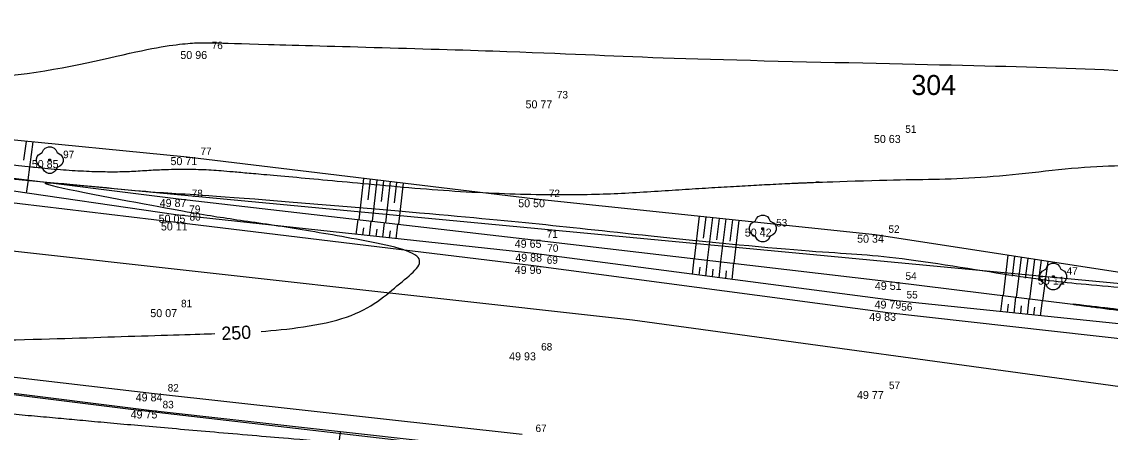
# Model space of a CAD drawing. Extents: x -704057 to -703795, y -1008732 to -1008584.
# Drawn here: x -703875.92 to -703835.12, y -1008671.22 to -1008655.82 of the extents above; entities that cross this region are included whole.
import ezdxf

# ---------------------------------------------------------------- set-up
doc = ezdxf.new("R2010")
doc.units = 0
for name, color, linetype in [('Z_body', 7, 'Continuous'), ('Z_body_cisla', 7, 'Continuous'), ('Z_body_vysky', 7, 'Continuous'), ('Z_katastr_cisla_pozemkove', 7, 'Continuous'), ('Z_katastr_hranice', 7, 'Continuous'), ('Z_katastr_hranice_KU', 7, 'Continuous'), ('Z_komunikace_zpevn_pl', 7, 'Continuous'), ('Z_teren_hrany_paty', 7, 'Continuous'), ('Z_vrstevnice_popis', 7, 'Continuous'), ('Z_vrstevnice_vedlejsi', 7, 'Continuous'), ('Z_zelen_jednotliva', 7, 'Continuous')]:
    doc.layers.add(name, color=color, linetype=linetype)

# ---------------------------------------------------------------- blocks, each defined once
blk = doc.blocks.new('POINT_DISPLAY')
blk.add_line((0, 0), (0, 0))
blk = doc.blocks.new('Z24')
for p, q in [((-0.23, 0.38), (-0.17, 0.45)), ((-0.17, 0.45), (-0.05, 0.5)), ((-0.05, 0.5), (0.05, 0.5)), ((0.05, 0.5), (0.17, 0.45)), ((0.17, 0.45), (0.23, 0.38)), ((-0.5, 0.05), (-0.47, 0.13)), ((-0.5, -0.05), (-0.5, 0.05)), ((-0.47, 0.13), (-0.42, 0.2)), ((-0.42, 0.2), (-0.28, 0.28)), ((-0.28, 0.28), (-0.23, 0.38)), ((-0.03, -0.03), (-0.03, 0.03)), ((-0.03, 0.03), (0.03, 0.03)), ((0.03, 0.03), (0.03, -0.03)), ((0.23, 0.38), (0.28, 0.28)), ((0.28, 0.28), (0.42, 0.2)), ((0.42, 0.2), (0.47, 0.13)), ((0.47, 0.13), (0.5, 0.05)), ((0.5, 0.05), (0.5, -0.05)), ((-0.45, -0.17), (-0.5, -0.05)), ((-0.38, -0.23), (-0.45, -0.17)), ((-0.28, -0.28), (-0.38, -0.23)), ((-0.2, -0.42), (-0.28, -0.28)), ((0.03, -0.03), (-0.03, -0.03)), ((0.28, -0.28), (0.2, -0.42)), ((0.38, -0.23), (0.28, -0.28)), ((0.45, -0.17), (0.38, -0.23)), ((0.5, -0.05), (0.45, -0.17)), ((-0.13, -0.47), (-0.2, -0.42)), ((-0.05, -0.5), (-0.13, -0.47)), ((0.05, -0.5), (-0.05, -0.5)), ((0.13, -0.47), (0.05, -0.5)), ((0.2, -0.42), (0.13, -0.47))]:
    blk.add_line(p, q)

msp = doc.modelspace()

# ---------------------------------------------------------------- linework, layer by layer
at = {"layer": 'Z_katastr_hranice'}
for p, q in [((-703892.72, -1008660.17), (-703821.1, -1008666.93)), ((-703907.73, -1008665.91), (-703871.83, -1008670.35)), ((-703871.83, -1008670.35), (-703828.51, -1008675.34))]:
    msp.add_line(p, q, dxfattribs=at)
at = {"layer": 'Z_katastr_hranice_KU'}
for p, q in [((-703906.73, -1008661.04), (-703853.02, -1008667)), ((-703853.02, -1008667), (-703796.88, -1008674.69))]:
    msp.add_line(p, q, dxfattribs=at)
at = {"layer": 'Z_komunikace_zpevn_pl'}
for p, q in [((-703870.13, -1008663.35), (-703882.46, -1008661.89)), ((-703856.74, -1008664.98), (-703870.13, -1008663.35)), ((-703843.45, -1008666.74), (-703856.74, -1008664.98)), ((-703832.57, -1008667.96), (-703843.45, -1008666.74)), ((-703883, -1008668.36), (-703870.95, -1008669.76)), ((-703870.95, -1008669.76), (-703857.16, -1008671.29))]:
    msp.add_line(p, q, dxfattribs=at)
at = {"layer": 'Z_teren_hrany_paty'}
for p, q in [((-703869.72, -1008660.9), (-703882.16, -1008659.68)), ((-703875.76, -1008660.31), (-703875.85, -1008661.02)), ((-703875.51, -1008660.33), (-703875.69, -1008661.75)), ((-703882.42, -1008660.9), (-703870.05, -1008662.47)), ((-703856.66, -1008662.48), (-703869.72, -1008660.9)), ((-703870.14, -1008663.06), (-703882.51, -1008661.26)), ((-703875.74, -1008662.25), (-703875.67, -1008661.76)), ((-703863.11, -1008661.7), (-703863.29, -1008663.25)), ((-703862.86, -1008661.73), (-703862.95, -1008662.5)), ((-703862.61, -1008661.76), (-703862.79, -1008663.3)), ((-703862.36, -1008661.79), (-703862.45, -1008662.56)), ((-703862.11, -1008661.82), (-703862.29, -1008663.36)), ((-703861.87, -1008661.85), (-703861.96, -1008662.62)), ((-703861.62, -1008661.88), (-703861.8, -1008663.42)), ((-703870.05, -1008662.47), (-703856.74, -1008664)), ((-703843.93, -1008663.81), (-703856.66, -1008662.48)), ((-703856.72, -1008664.52), (-703870.14, -1008663.06)), ((-703863.38, -1008663.8), (-703863.31, -1008663.24)), ((-703850.53, -1008663.12), (-703850.71, -1008664.71)), ((-703850.28, -1008663.15), (-703850.37, -1008663.94)), ((-703850.03, -1008663.17), (-703850.22, -1008664.77)), ((-703849.78, -1008663.2), (-703849.87, -1008664)), ((-703849.53, -1008663.22), (-703849.72, -1008664.82)), ((-703849.28, -1008663.25), (-703849.38, -1008664.05)), ((-703863.13, -1008663.82), (-703863.1, -1008663.55)), ((-703862.88, -1008663.85), (-703862.82, -1008663.3)), ((-703862.63, -1008663.88), (-703862.6, -1008663.6)), ((-703862.38, -1008663.9), (-703862.32, -1008663.36)), ((-703862.14, -1008663.93), (-703862.1, -1008663.66)), ((-703861.89, -1008663.96), (-703861.82, -1008663.42)), ((-703849.04, -1008663.28), (-703849.22, -1008664.88)), ((-703856.74, -1008664), (-703843.29, -1008665.58)), ((-703832.19, -1008665.63), (-703843.93, -1008663.81)), ((-703843.25, -1008666.28), (-703856.72, -1008664.52)), ((-703850.77, -1008665.3), (-703850.71, -1008664.71)), ((-703850.28, -1008665.36), (-703850.21, -1008664.77)), ((-703849.78, -1008665.43), (-703849.71, -1008664.83)), ((-703849.29, -1008665.49), (-703849.22, -1008664.88)), ((-703838.95, -1008664.58), (-703839.13, -1008666.09)), ((-703838.7, -1008664.62), (-703838.79, -1008665.37)), ((-703838.45, -1008664.66), (-703838.64, -1008666.15)), ((-703838.21, -1008664.7), (-703838.3, -1008665.44)), ((-703837.96, -1008664.74), (-703838.14, -1008666.22)), ((-703837.71, -1008664.77), (-703837.8, -1008665.51)), ((-703837.46, -1008664.81), (-703837.65, -1008666.28)), ((-703850.53, -1008665.33), (-703850.49, -1008665.03)), ((-703850.03, -1008665.39), (-703850, -1008665.1)), ((-703849.53, -1008665.46), (-703849.5, -1008665.16)), ((-703843.29, -1008665.58), (-703832.35, -1008666.93)), ((-703839.22, -1008666.69), (-703839.14, -1008666.09)), ((-703832.45, -1008667.39), (-703843.25, -1008666.28)), ((-703838.97, -1008666.72), (-703838.93, -1008666.42)), ((-703838.72, -1008666.75), (-703838.65, -1008666.15)), ((-703838.47, -1008666.77), (-703838.44, -1008666.48)), ((-703838.22, -1008666.8), (-703838.15, -1008666.21)), ((-703837.98, -1008666.82), (-703837.94, -1008666.53)), ((-703837.73, -1008666.85), (-703837.66, -1008666.28)), ((-703871.14, -1008670.4), (-703883.02, -1008668.93)), ((-703857.13, -1008671.96), (-703871.14, -1008670.4)), ((-703863.99, -1008671.2), (-703864.17, -1008672.74))]:
    msp.add_line(p, q, dxfattribs=at)
at = {"layer": 'Z_vrstevnice_popis'}
for points in [[(-703900.886, -1008655.959), (-703899.024, -1008656.26), (-703894.071, -1008657.056), (-703890.313, -1008657.487), (-703881.983, -1008657.824), (-703876.324, -1008658.109), (-703871.084, -1008656.76), (-703869.237, -1008656.583), (-703868.601, -1008656.623), (-703856.36, -1008656.952), (-703852.392, -1008657.193), (-703842.819, -1008657.404), (-703836.655, -1008657.542), (-703831.19, -1008657.812), (-703826.999, -1008658.179), (-703824.254, -1008658.442), (-703823.966, -1008658.47)], [(-703866.94, -1008667.434), (-703866.032, -1008667.372), (-703863.34, -1008667.075), (-703861.725, -1008665.569), (-703860.311, -1008664.545), (-703863.717, -1008663.91), (-703866.193, -1008663.489), (-703868.465, -1008663.178), (-703870.115, -1008662.896), (-703877.36, -1008661.542), (-703870.689, -1008662.276), (-703869.999, -1008662.227), (-703861.026, -1008662.976), (-703856.707, -1008663.374), (-703852.831, -1008663.809), (-703845.902, -1008664.503), (-703843.668, -1008664.535), (-703838.357, -1008665.417), (-703836.381, -1008665.655), (-703832.233, -1008665.983), (-703829.782, -1008666.213), (-703825.08, -1008666.738), (-703823.448, -1008666.921)], [(-703935.451, -1008665.426), (-703935.149, -1008665.04), (-703935.119, -1008664.898), (-703935.079, -1008664.688), (-703934.778, -1008664.597), (-703933.704, -1008664.644), (-703930.729, -1008663.86), (-703930.56, -1008663.863), (-703922.686, -1008664.709), (-703917.99, -1008665.148), (-703912.22, -1008665.818), (-703907.01, -1008666.385), (-703897.89, -1008667.322), (-703895.624, -1008667.536), (-703894.683, -1008667.62), (-703889.646, -1008668.109), (-703886.88, -1008668.055), (-703885.948, -1008667.981), (-703882.942, -1008667.846), (-703876.005, -1008667.766), (-703871.926, -1008667.612), (-703869.247, -1008667.54), (-703868.688, -1008667.52)]]:
    msp.add_open_spline(points, degree=3, dxfattribs=at)
at = {"layer": 'Z_vrstevnice_vedlejsi'}
for points in [[(-703944.218, -1008669.537), (-703942.215, -1008669.847), (-703941.835, -1008669.79), (-703940.983, -1008669.911), (-703940.538, -1008669.059), (-703940.441, -1008669.011), (-703939.659, -1008668.87), (-703938.392, -1008666.573), (-703937.218, -1008665.198), (-703936.994, -1008664.158), (-703936.811, -1008663.182), (-703935.504, -1008662.788), (-703930.851, -1008662.989), (-703930.683, -1008662.945), (-703930.514, -1008662.948), (-703928.53, -1008663.14), (-703926.451, -1008662.869), (-703924.285, -1008662.962), (-703918.453, -1008660.188), (-703917.529, -1008662.583), (-703908.804, -1008661.73), (-703914.417, -1008658.58), (-703914.255, -1008657.775), (-703916.458, -1008657.408), (-703916.075, -1008656.975), (-703916.505, -1008656.883), (-703916.435, -1008655.703), (-703915.746, -1008656.007), (-703915.438, -1008656.225), (-703913.541, -1008656.36), (-703913.202, -1008656.502), (-703907.93, -1008657.256), (-703905.824, -1008657.417), (-703900.033, -1008658.024), (-703894.345, -1008658.848), (-703890.179, -1008659.57), (-703887.702, -1008659.871), (-703882.266, -1008660.175), (-703878.347, -1008660.959), (-703873.149, -1008661.531), (-703869.803, -1008661.293), (-703867.148, -1008661.514), (-703856.66, -1008662.48), (-703848.555, -1008661.935), (-703843.582, -1008661.747), (-703840.018, -1008661.713), (-703835.656, -1008661.182), (-703832.168, -1008661.259), (-703831.497, -1008661.293), (-703819.488, -1008662.346), (-703817.521, -1008662.543), (-703807.841, -1008663.114), (-703805.78, -1008663.132)], [(-703806.645, -1008669.413), (-703810.064, -1008669.091), (-703818.896, -1008668.231), (-703821.949, -1008667.886), (-703832.348, -1008666.911), (-703832.429, -1008666.905), (-703837.82, -1008666.255), (-703832.713, -1008666.908), (-703832.355, -1008666.952), (-703825.705, -1008667.99), (-703819.056, -1008669.026), (-703815.993, -1008669.415), (-703810.462, -1008670.24), (-703806.87, -1008671.09), (-703808.766, -1008673.591), (-703809.75, -1008673.886), (-703817.454, -1008673.52), (-703819.628, -1008673.248), (-703826.836, -1008673.24), (-703833.27, -1008673.353), (-703835.286, -1008673.278), (-703844.44, -1008672.81), (-703850.152, -1008672.821), (-703855.806, -1008672.275), (-703857.13, -1008672.165), (-703860.162, -1008671.947), (-703871.237, -1008671.005), (-703876.973, -1008670.473), (-703883.276, -1008669.953), (-703888.652, -1008669.207), (-703892.007, -1008668.787), (-703895.701, -1008668.459), (-703900.931, -1008667.965), (-703907.22, -1008668.487), (-703913.351, -1008668.979), (-703918.495, -1008669.549), (-703927.701, -1008668.863), (-703930.6, -1008669.724), (-703932.124, -1008670.909), (-703936.972, -1008673.376)]]:
    msp.add_open_spline(points, degree=2, dxfattribs=at)

# ---------------------------------------------------------------- block references
at = {"layer": 'Z_body'}
for p in [(-703869.3, -1008656.92), (-703856.36, -1008658.77), (-703843.3, -1008660.07), (-703874.87, -1008661.01), (-703869.72, -1008660.9), (-703870.05, -1008662.47), (-703856.66, -1008662.48), (-703870.14, -1008663.06), (-703870.13, -1008663.35), (-703848.14, -1008663.58), (-703856.74, -1008664), (-703843.93, -1008663.81), (-703856.72, -1008664.52), (-703856.74, -1008664.98), (-703843.29, -1008665.58), (-703837.25, -1008665.38), (-703843.25, -1008666.28), (-703870.45, -1008666.6), (-703843.45, -1008666.74), (-703856.95, -1008668.22), (-703870.95, -1008669.76), (-703843.91, -1008669.67), (-703871.14, -1008670.4)]:
    msp.add_blockref('POINT_DISPLAY', p, dxfattribs=at)
at = {"layer": 'Z_zelen_jednotliva'}
for p in [(-703874.87, -1008661.01), (-703848.14, -1008663.58), (-703837.25, -1008665.38)]:
    msp.add_blockref('Z24', p, dxfattribs=at)

# ---------------------------------------------------------------- texts
at = {"layer": 'Z_body_cisla'}
for s, p in [('76', (-703868.8, -1008656.85)), ('73', (-703855.86, -1008658.7)), ('51', (-703842.8, -1008659.99)), ('97', (-703874.37, -1008660.94)), ('77', (-703869.22, -1008660.82)), ('78', (-703869.55, -1008662.4)), ('72', (-703856.16, -1008662.4)), ('79', (-703869.64, -1008662.99)), ('80', (-703869.63, -1008663.28)), ('53', (-703847.64, -1008663.5)), ('71', (-703856.24, -1008663.93)), ('52', (-703843.43, -1008663.74)), ('70', (-703856.22, -1008664.45)), ('69', (-703856.24, -1008664.9)), ('54', (-703842.79, -1008665.5)), ('47', (-703836.75, -1008665.31)), ('55', (-703842.75, -1008666.2)), ('81', (-703869.95, -1008666.53)), ('56', (-703842.95, -1008666.66)), ('68', (-703856.45, -1008668.15)), ('57', (-703843.41, -1008669.6)), ('82', (-703870.45, -1008669.69)), ('83', (-703870.64, -1008670.32)), ('67', (-703856.66, -1008671.21))]:
    msp.add_text(s, height=0.28, dxfattribs=at).set_placement(p)
at = {"layer": 'Z_body_vysky'}
for s, p in [('50 96', (-703869.975, -1008657.22)), ('50 77', (-703857.035, -1008659.07)), ('50 63', (-703843.975, -1008660.37)), ('50 85', (-703875.545, -1008661.31)), ('50 71', (-703870.345, -1008661.2)), ('49 87', (-703870.75, -1008662.77)), ('50 50', (-703857.31, -1008662.78)), ('50 05', (-703870.79, -1008663.36)), ('50 11', (-703870.705, -1008663.65)), ('50 42', (-703848.815, -1008663.88)), ('49 65', (-703857.44, -1008664.3)), ('50 34', (-703844.605, -1008664.11)), ('49 88', (-703857.42, -1008664.82)), ('49 96', (-703857.44, -1008665.28)), ('49 51', (-703843.94, -1008665.88)), ('50 11', (-703837.825, -1008665.68)), ('49 79', (-703843.95, -1008666.58)), ('50 07', (-703871.1, -1008666.9)), ('49 83', (-703844.15, -1008667.04)), ('49 93', (-703857.65, -1008668.52)), ('49 84', (-703871.65, -1008670.06)), ('49 77', (-703844.61, -1008669.97)), ('49 75', (-703871.84, -1008670.7))]:
    msp.add_text(s, height=0.3, dxfattribs=at).set_placement(p)
at = {"layer": 'Z_katastr_cisla_pozemkove'}
msp.add_text('304', height=0.75, dxfattribs=at).set_placement((-703842.57, -1008658.57))
at = {"layer": 'Z_vrstevnice_popis'}
msp.add_text('250', height=0.5, rotation=2.7472, dxfattribs=at).set_placement((-703868.426, -1008667.763))

doc.saveas('drawing.dxf')
